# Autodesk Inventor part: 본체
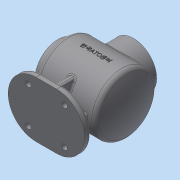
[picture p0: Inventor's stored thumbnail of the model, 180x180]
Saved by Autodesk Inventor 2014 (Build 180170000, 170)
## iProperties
Created: 2023-01
Part Number: 본체
Material: 일반
Document SubType Name: Modeling
Designer: dg
Density: 1 g/cm^3
Appearance: 기본값
Author: dg
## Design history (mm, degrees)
sketch "스케치1"
  geometry: L1 (-61, 0)-(61, 0); L2 (50.087, 50)-(-51, 50); L3 (-51, 50)-(-51, 38); L4 (-51, 38)-(-61, 38); L5 (-61, 38)-(-61, 0); L6 (-44, 27)-(-44, 45); L7 (-44, 45)-(46.83, 45); L8 (-61, 27)-(-44, 27); A1 r 120 centre (-59, 0) between (61, 0) and (50.087, 50); A2 r 115 centre (-59, 0) between (56, 0) and (46.83, 45); 2 further points
  constraints: 16 end point, 4 point on circle, 3 point on line, 2 centre point, 2 horizontal, 2 parallel, 2 perpendicular, 1 coincident, 1 midpoint, 1 vertical
  dimensions: "d0" = 122 distance of L1.start L1.end; "d1" = 120 radius of A1; "d2" = 100 diameter of L2 L1; "d3" = 76 diameter of L4 L1; "d5" = 5 radial gap between concentric circles of A1 A2; "d6" = 5 distance between parallel lines of L2 L7; "d7" = 51 distance from line of L3 point (0, 0); "d8" = 54 diameter of L8 L1; "d9" = 17 distance of L8.start L6.start
revolve "회전1" sketch "스케치1" stored, may be unused: angle "d10" = 90 deg
fillet "모깎기1" dims "d11" = 8
node "작업 평면1"
sketch "스케치2"
  geometry: L1 (-17, 0)-(17, 0); L2 (-17, -46)-(17, -46); L3 (17, 46)-(-17, 46); A1 r 46 centre (-17, 0) between (-17, 46) and (-17, -46); A2 r 46 centre (17, 0) between (17, -46) and (17, 46); 2 further points
  constraints: 8 end point, 4 point on circle, 4 tangent, 2 centre point, 1 coincident, 1 horizontal, 1 midpoint, 1 parallel
  dimensions: "d14" = 92 distance between parallel lines of L2 L3; "d15" = 126 dimension on A2 A1
extrude "돌출1" join sketch "스케치2" distance "d23" = 10; taper "d24" = 0 deg
node "작업 평면3"
sketch "스케치3"
  geometry: L1 (51, 42)-(51, -42) reference; L2 (-52.243, -45)-(-52.243, 45) reference; C1 r 38 at (0, 0); 2 further points
  constraints: 1 centre point, 1 coincident, 1 horizontal alignment, 1 midpoint
  dimensions: "d26" = 76 diameter of C1; "d93" = 51 distance from line of point (0, 0) L1
extrude "돌출2" join sketch "스케치3" stored distance "d27" = 10; taper "d28" = 0 deg
hole "구멍1" diameter "d31" = 54; stored, may be unused: countersink angle "d35" = 90 deg, drill point angle "d37" = 118 deg; dims "d29" = 10, "d30" = 10, "d32" = 6, "d33" = 4, "d34" = 2, "d36" = 53.5
sketch "스케치4"
  geometry: L1 (-5, 35)-(5, 35); L2 (5, 35)-(5, -35); L3 (5, -35)-(-5, -35); L4 (-5, -35)-(-5, 35); 3 further points
  constraints: 8 end point, 2 midpoint, 2 parallel, 1 horizontal, 1 horizontal alignment, 1 perpendicular, 1 vertical alignment
  dimensions: "d38" = 10 distance of L1.start L1.end; "d39" = 70 distance of L3.end L1.start
extrude "돌출3" join sketch "스케치4" stored distance "d40" = 10; taper "d41" = 0 deg
sketch "스케치5"
  geometry: L1 (-5, -70)-(-5, -35.707) reference; L2 (-43, -50)-(44.827, -50) reference; L3 (-43, -50)-(44.827, -50) reference; L4 (5, -70)-(5, -35.707) reference; L5 (-34.641, -50)-(-40, -70); L6 (-17, -70)-(-63, -70) reference; L7 (46.83, -45)-(-44, -45) reference; L8 (17, -80)-(-17, -80) reference; L9 (0, -45)-(0, -80); 1 further point
  constraints: 4 end point, 2 midpoint, 2 point on line
  dimensions: "d42" = 105 deg angle of L6 L5; "d43" = 40 distance from line of L9 L5.end; "d44" = 23 distance of L6.end L5.end
feature "리브1" sketch "스케치5" dims "d45" = 1, "d46" = 10, "d47" = 0, "d48" = 0, "d49" = 1, "d50" = 1
fillet "모깎기2" dims "d51" = 3
fillet "모깎기3" dims "d52" = 3
fillet "모깎기4" dims "d53" = 3
sketch "스케치6"
  geometry: C1 r 4.5 at (-30, 30); C2 r 4.5 at (30, 30); C3 r 4.5 at (30, -30); C4 r 4.5 at (-30, -30); 1 further point
  constraints: 4 centre point, 3 equal radius, 2 vertical alignment
  dimensions: "d54" = 30 horizontal distance of point (0, 0) C1.centre; "d55" = 60 distance of C4.centre C1.centre; "d56" = 30 horizontal distance of point (0, 0) C1.centre; "d57" = 30 horizontal distance of point (0, 0) C2.centre; "d58" = 30 horizontal distance of point (0, 0) C2.centre; "d59" = 30 horizontal distance of C3.centre point (0, 0); "d60" = 9 diameter of C1
extrude "돌출4" cut sketch "스케치6" distance "d61" = 10; taper "d62" = 0 deg
chamfer "모따기1" distance "d63" = 1; stored, may be unused: second distance "d64" = 2, angle "d65" = 45 deg
sketch "스케치7"
  geometry: C1 r 38 at (0, 0) reference; 1 further point
  constraints: 1 vertical alignment
  dimensions: "d66" = 32.5 distance of C1.centre point (0, 32.5)
hole "구멍2" sketch "스케치7" at (0, 32.5) diameter "d67" = 3.242; stored, may be unused: countersink angle "d71" = 82 deg, drill point angle "d73" = 118 deg; dims "d68" = 8, "d69" = 3.023, "d70" = 2, "d72" = 10
sketch "스케치8"
  geometry: C1 r 38 at (0, 0) reference; 1 further point
  constraints: 1 vertical alignment
  dimensions: "d77" = 32.5 distance of point (0, 32.5) C1.centre
hole "구멍3" sketch "스케치8" at (0, 32.5) diameter "d78" = 3.242; stored, may be unused: countersink angle "d82" = 82 deg, drill point angle "d84" = 118 deg; dims "d79" = 8, "d80" = 3.023, "d81" = 2, "d83" = 10
fillet "모깎기5" dims "d88" = 3
node "작업 평면4"
sketch "스케치10"
  geometry: L1 (-60.544, -38)-(-60.544, 38) reference; L2 (63.456, -80)-(17.456, -80) reference; 2 further points
  constraints: 1 other
  dimensions: "d89" = 63 distance from line of L1 point (2.456, 0); "d90" = 80 distance from line of L2 point (2.456, 0)
feature "엠보싱1" sketch "스케치10" dims "d0" = 122, "d1" = 120, "d2" = 100, "d3" = 76, "d5" = 5, "d6" = 5, "d7" = 51, "d8" = 54, "d9" = 17, "d91" = 0.5, "d92" = 0
node "솔리드1"
mirror "대칭1"
pattern_circular "원형 패턴1" dims angle "d75" = 360 deg
pattern_circular "원형 패턴2" dims angle "d86" = 360 deg
node "투영된 루프1"
other parameters: "d25" = 144
